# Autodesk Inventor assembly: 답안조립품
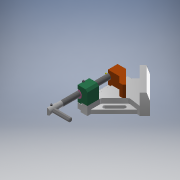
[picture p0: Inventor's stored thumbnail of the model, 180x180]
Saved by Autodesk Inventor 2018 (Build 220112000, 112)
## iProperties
Created: 2020-05
Part Number: 답안조립품
Document SubType Name: Assembly
Designer: Administrator
Author: Administrator
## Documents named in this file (11)
- C:\Users\Administrator\Desktop\700506V1062\답안조립품.iam
- C:\Users\Administrator\Desktop\700506V1062\조.ipt
- C:\Users\Administrator\Desktop\700506V1062\베이스.ipt
- C:\Users\Administrator\Desktop\700506V1062\서포트.ipt
- C:\Users\Administrator\Desktop\700506V1062\부시.ipt
- C:\Users\Administrator\Desktop\700506V1062\리드스크류.ipt
- C:\Users\Administrator\Desktop\700506V1062\핸들.ipt
- C:\Users\Administrator\Desktop\700506V1062\볼트 M4x16.ipt
- C:\Users\Administrator\Desktop\700506V1062\평행 핀 2.5x24.ipt
- C:\Users\Administrator\Desktop\700506V1062\멈춤나사 M4x10.ipt
- C:\Users\Administrator\Desktop\700506V1062\멈춤나사 M4x5.ipt
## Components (1 placed, 1 different names)
1. 핸들:1
